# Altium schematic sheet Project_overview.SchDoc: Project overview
size A4; Date: Not used; ApprovedBy: Not used; CheckedBy: Not used; Author: Not used; CompanyName: STMicroelectronics; DrawnBy: Not used; Engineer: Not used; Organization: Not used; Address1: Not used; Address2: Not used; Address3: Not used; Address4: Not used; DocumentNumber: Not used; Revision: Not used; SheetNumber: 1; SheetTotal: 7
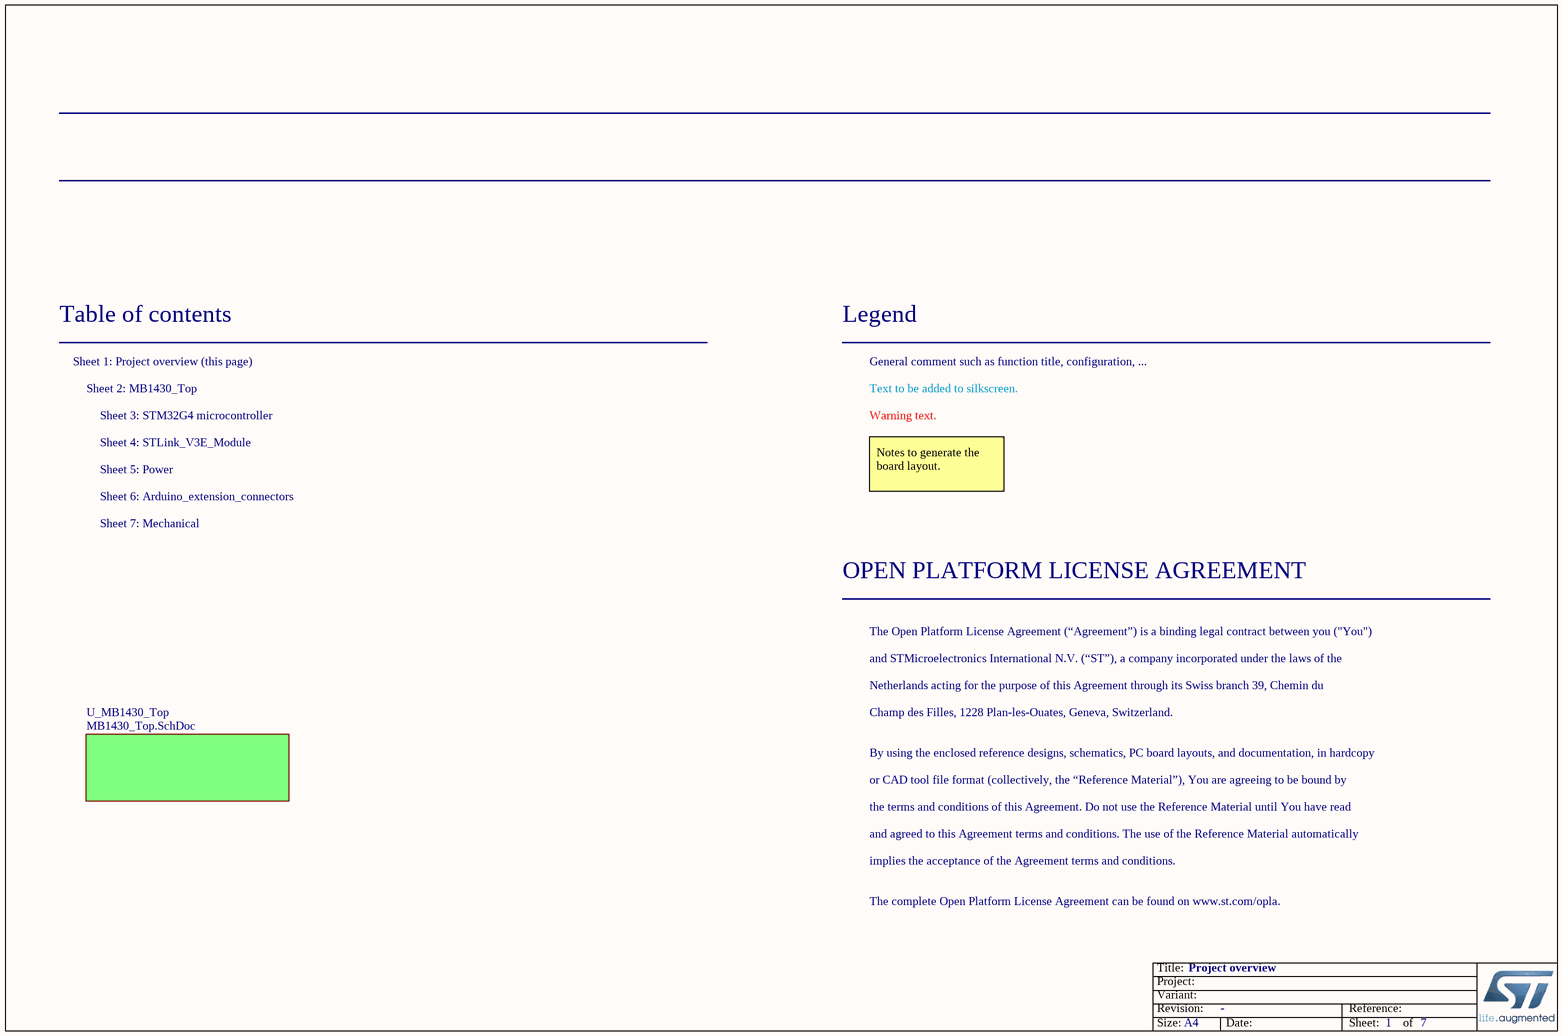
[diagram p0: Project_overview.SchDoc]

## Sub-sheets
U_MB1430_Top = MB1430_Top.SchDoc: no entries

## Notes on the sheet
- Table of contents
- Sheet 1: Project overview (this page)
- Legend
- General comment such as function title, configuration, ...
- Sheet 2: MB1430_Top
- Sheet 4: STLink_V3E_Module
- Sheet 3: STM32G4 microcontroller
- Text to be added to silkscreen.
- Warning text.
- Sheet 6: Arduino_extension_connectors
- Sheet 5: Power
- Notes to generate the board layout.
- Sheet 7: Mechanical
- OPEN PLATFORM LICENSE AGREEMENT
- The Open Platform License Agreement (“Agreement”) is a binding legal contract between you ("You")
- and STMicroelectronics International N.V. (“ST”), a company incorporated under the laws of the
- Netherlands acting for the purpose of this Agreement through its Swiss branch 39, Chemin du
- Champ des Filles, 1228 Plan-les-Ouates, Geneva, Switzerland.
- By using the enclosed reference designs, schematics, PC board layouts, and documentation, in hardcopy
- or CAD tool file format (collectively, the “Reference Material”), You are agreeing to be bound by
- the terms and conditions of this Agreement. Do not use the Reference Material until You have read
- and agreed to this Agreement terms and conditions. The use of the Reference Material automatically
- implies the acceptance of the Agreement terms and conditions.
- The complete Open Platform License Agreement can be found on www.st.com/opla.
